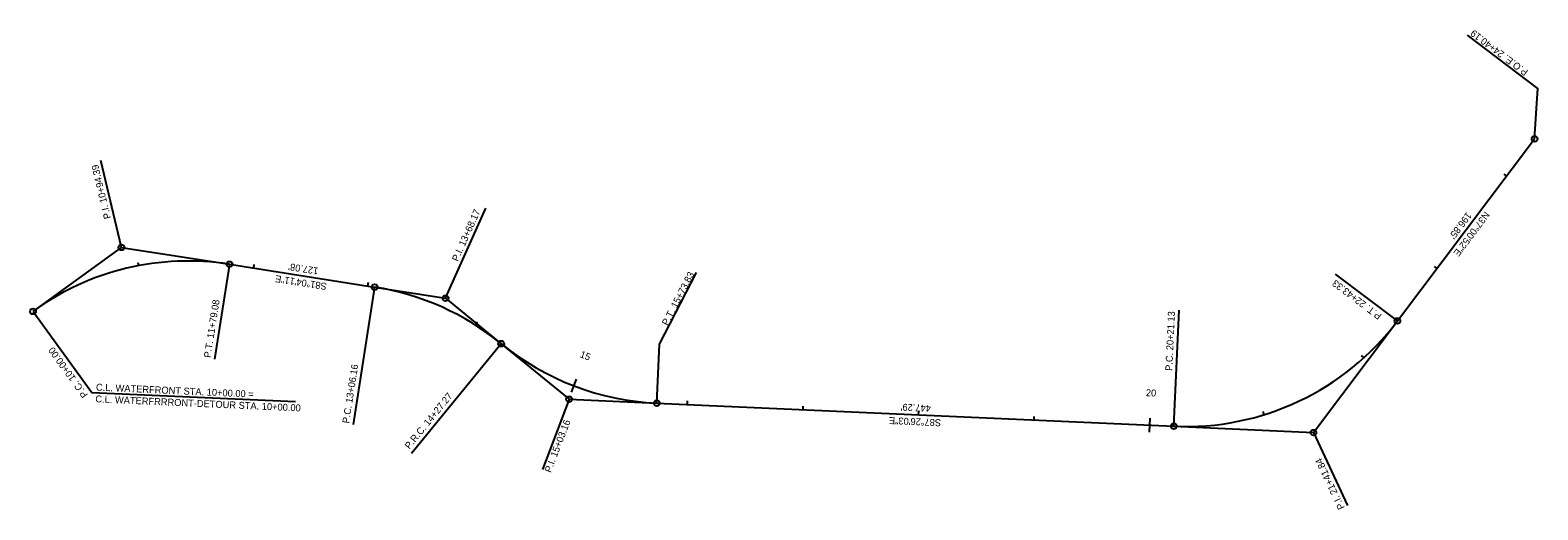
# Model space of a CAD drawing. Extents: x 643763 to 653976, y 408262 to 431605.
# Drawn here: x 652673 to 653976, y 408262 to 408676 of the extents above; entities that cross this region are included whole.
import ezdxf

# ---------------------------------------------------------------- set-up
doc = ezdxf.new("R2010")
doc.units = 0
for name, color, linetype in [('R_Horz Alg Main', 7, 'Continuous'), ('R_Horz Alg Main Control', 7, 'Continuous'), ('R_Horz Alg Main Station', 7, 'Continuous'), ('R_No Plot', 7, 'Continuous')]:
    doc.layers.add(name, color=color, linetype=linetype)

msp = doc.modelspace()

# ---------------------------------------------------------------- linework, layer by layer
at = {"layer": 'R_Horz Alg Main'}
for p, q in [((653854.6, 408424.9), (653973.2, 408582.1)), ((652845.1, 408473.9), (652970.6, 408454.1)), ((653214.5, 408353.9), (653661.4, 408333.9))]:
    msp.add_line(p, q, dxfattribs=at)
for centre in [(653973.2, 408582.1), (652845.1, 408473.9), (652970.6, 408454.1), (652675.3, 408433.2), (653854.6, 408424.9), (653079.9, 408405.3), (653214.5, 408353.9), (653661.4, 408333.9)]:
    msp.add_circle(centre, 2.5, dxfattribs=at)
for centre, start, end in [((652809.5, 408247.5), 81.0698, 125.8396), ((652935.1, 408227.7), 50.7931, 81.0698), ((653671.6, 408562.9), 267.4341, 322.9855), ((653224.8, 408582.9), 230.7931, 267.4341)]:
    msp.add_arc(centre, 229.2, start, end, dxfattribs=at)
at = {"layer": 'R_Horz Alg Main Control'}
for points in [[(653973.2, 408582.1), (653976, 408625.8), (653915.1, 408671.7)], [(652751.8, 408488.5), (652733.9, 408563.6)], [(653031.9, 408444.5), (653066.6, 408522.3)], [(652675.3, 408433.2), (652751.8, 408488.5), (652845.1, 408473.9)], [(652845.1, 408473.9), (652832.2, 408391.8)], [(653214.5, 408353.9), (653216.8, 408404.9), (653248.8, 408466.9)], [(653854.6, 408424.9), (653801.2, 408465.2)], [(652970.6, 408454.1), (652952, 408335.6)], [(652970.6, 408454.1), (653031.9, 408444.5), (653079.9, 408405.3)], [(652675.3, 408433.2), (652726, 408363.1), (652902.2, 408355.3)], [(653661.4, 408333.9), (653665.9, 408434.3)], [(653661.4, 408333.9), (653782, 408328.5), (653854.6, 408424.9)], [(653079.9, 408405.3), (653002.4, 408310.3)], [(653079.9, 408405.3), (653138.7, 408357.3), (653214.5, 408353.9)], [(653138.7, 408357.3), (653115.6, 408296.7)], [(653782, 408328.5), (653811.6, 408265.5)]]:
    msp.add_lwpolyline(points, dxfattribs=at)
for centre in [(652751.8, 408488.5), (653031.9, 408444.5), (653138.7, 408357.3), (653782, 408328.5)]:
    msp.add_circle(centre, 2.5, dxfattribs=at)
at = {"layer": 'R_Horz Alg Main Station'}
for points in [[(653946.6, 408551.8), (653949, 408550)], [(652765.8, 408475.5), (652766.4, 408472.5)], [(652866.2, 408473.6), (652865.8, 408470.6)], [(653886.4, 408472), (653888.8, 408470.1)], [(652965, 408458.1), (652964.5, 408455.1)], [(653059.4, 408423.8), (653057.8, 408421.3)], [(653823.4, 408395.2), (653825.5, 408393)], [(653144.7, 408374.6), (653140.4, 408363.4)], [(653240.8, 408355.8), (653240.7, 408352.8)], [(653340.7, 408351.3), (653340.6, 408348.3)], [(653440.6, 408346.8), (653440.5, 408343.8)], [(653738.3, 408346.8), (653739.2, 408343.9)], [(653540.5, 408342.3), (653540.4, 408339.3)], [(653640.5, 408340.9), (653640, 408328.9)]]:
    msp.add_lwpolyline(points, dxfattribs=at)

# ---------------------------------------------------------------- texts
at = {"layer": 'R_Horz Alg Main Control'}
for s, rotation, p in [('P.O.E. 24+40.19', 142.9855, (653968.2, 408641)), ('P.I. 10+94.39', 103.4547, (652742.7, 408513.8)), ('P.I. 13+68.17', 65.9314, (653042.6, 408475.8)), ('P.T. 15+73.83', 62.708, (653223.9, 408420.4)), ('P.T. 22+43.33', 142.9855, (653841.6, 408430.4)), ('P.T. 11+79.08', 81.0698, (652828.8, 408392.8)), ('P.C. 20+21.13', 87.4341, (653660, 408381.7)), ('P.C. 10+00.00', 125.8396, (652723.1, 408361.2)), ('P.C. 13+06.16', 81.0698, (652948.5, 408336.1)), ('C.L. WATERFRONT STA. 10+00.00 =', 357.4341, (652729.6, 408364.8)), ('C.L. WATERFRRRONT-DETOUR STA. 10+00.00', 357.4341, (652729.1, 408354.7)), ('P.R.C. 14+27.27', 50.7931, (653000.7, 408313.7)), ('P.I. 15+03.16', 69.1136, (653122.9, 408293.4)), ('P.I. 21+41.84', 115.2098, (653809.2, 408263.7))]:
    msp.add_text(s, height=6, rotation=rotation, dxfattribs=at).set_placement(p)
at = {"layer": 'R_Horz Alg Main Station'}
for s, rotation, p in [('15', 338.9754, (653147.5, 408393.8)), ('20', 357.4341, (653637.1, 408360))]:
    msp.add_text(s, height=6, rotation=rotation, dxfattribs=at).set_placement(p)
at = {"layer": 'R_No Plot'}
for s, rotation, p in [("196.85'", 232.9855, (653914.6, 408519.4)), ('N37%%d00\'52"E', 232.9855, (653930.1, 408520)), ('S81%%d04\'11"E', 171.0698, (652929.6, 408457.5)), ("127.08'", 171.0698, (652922.3, 408470.8)), ("447.29'", 177.4341, (653451.5, 408352.3)), ('S87%%d26\'03"E', 177.4341, (653460.3, 408339.9))]:
    msp.add_text(s, height=6, rotation=rotation, dxfattribs=at).set_placement(p)

doc.saveas('drawing.dxf')
